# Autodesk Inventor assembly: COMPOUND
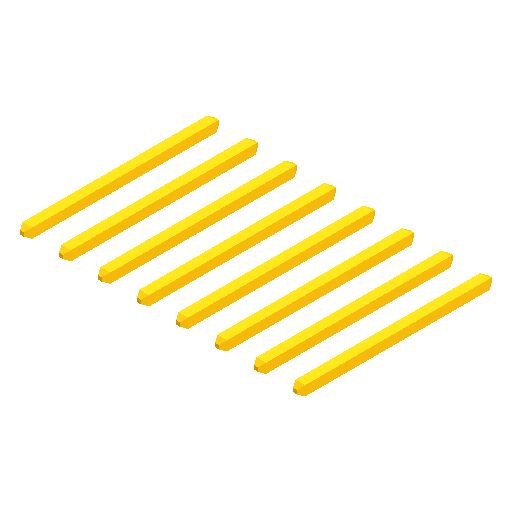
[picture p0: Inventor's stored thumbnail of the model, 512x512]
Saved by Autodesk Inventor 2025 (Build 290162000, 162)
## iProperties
Created: 2025-05
Part Number: COMPOUND
Document SubType Name: Assembly
Designer: R5800u
Author: R5800u
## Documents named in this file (9)
- C:\Users\R5800u\Desktop\drone\c3\ESP32-C3 Super Mini breakout expansion board module -Assembly\COMPOUND.iam
- C:\Users\R5800u\Desktop\drone\c3\ESP32-C3 Super Mini breakout expansion board module -Assembly\COMPOUND.ipt
- C:\Users\R5800u\Desktop\drone\c3\ESP32-C3 Super Mini breakout expansion board module -Assembly\COMPOUND_1.ipt
- C:\Users\R5800u\Desktop\drone\c3\ESP32-C3 Super Mini breakout expansion board module -Assembly\COMPOUND_2.ipt
- C:\Users\R5800u\Desktop\drone\c3\ESP32-C3 Super Mini breakout expansion board module -Assembly\COMPOUND_3.ipt
- C:\Users\R5800u\Desktop\drone\c3\ESP32-C3 Super Mini breakout expansion board module -Assembly\COMPOUND_4.ipt
- C:\Users\R5800u\Desktop\drone\c3\ESP32-C3 Super Mini breakout expansion board module -Assembly\COMPOUND_5.ipt
- C:\Users\R5800u\Desktop\drone\c3\ESP32-C3 Super Mini breakout expansion board module -Assembly\COMPOUND_6.ipt
- C:\Users\R5800u\Desktop\drone\c3\ESP32-C3 Super Mini breakout expansion board module -Assembly\COMPOUND_7.ipt
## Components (8 placed, 8 different names)
1. 2
2. 3
3. 4
4. 5
5. 6
6. 7
7. 8
8. 9
